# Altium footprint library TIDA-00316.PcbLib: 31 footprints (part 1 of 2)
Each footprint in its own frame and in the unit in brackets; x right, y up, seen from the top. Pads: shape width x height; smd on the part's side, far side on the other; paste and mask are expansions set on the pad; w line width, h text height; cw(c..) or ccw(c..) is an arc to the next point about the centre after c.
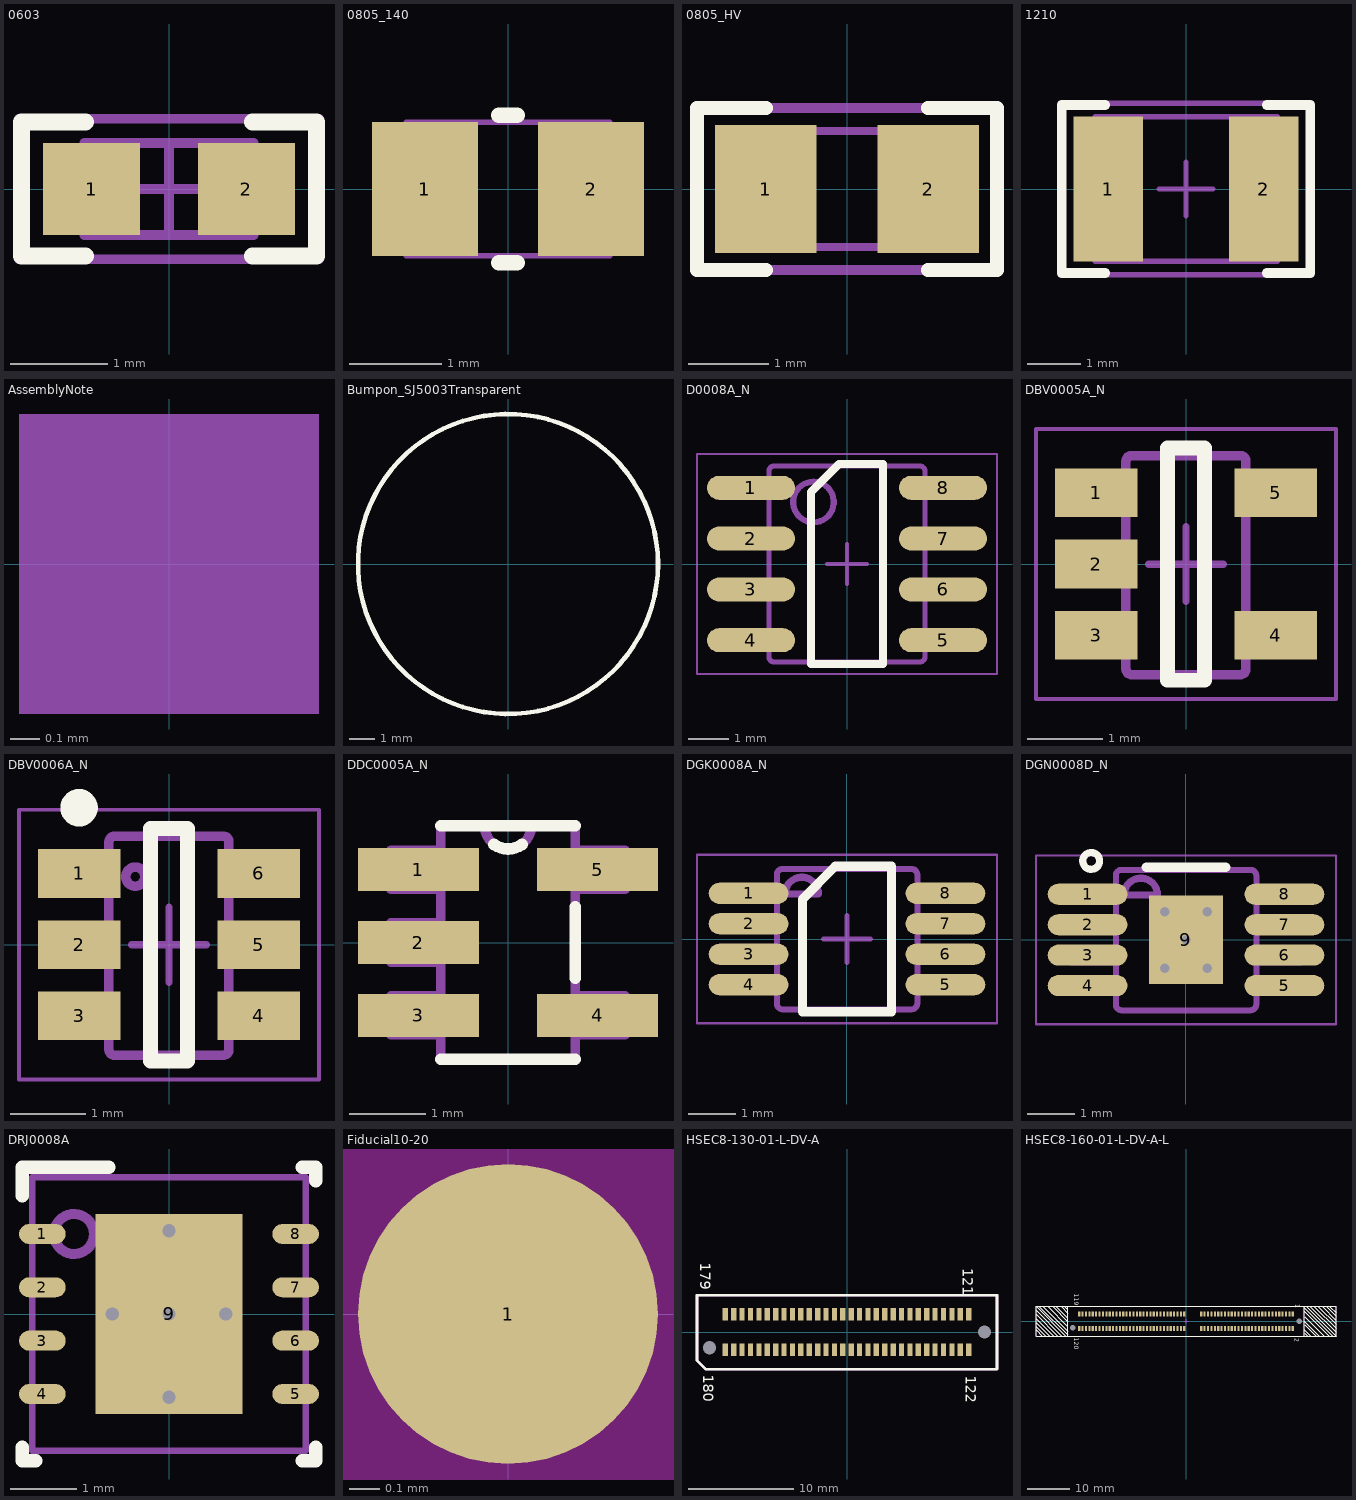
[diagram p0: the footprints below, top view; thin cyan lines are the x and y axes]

## 0603 [mm] "0603 from SM-752 data"
height 0.85
pads (2):
  rect 1x0.95 smd: 1(-0.8,0) 2(0.8,0)
Top Overlay:
  lines w0.178: -0.864,-0.691 -1.524,-0.691 -1.524,0.693 -0.864,0.693 ; 0.864,-0.691 1.524,-0.691 1.524,0.693 0.864,0.693
Mechanical 5:
  lines w0.1: -1.55,-0.725 1.55,-0.725 1.55,0.725 -1.55,0.725 -1.55,-0.725
  text ".Designator" at 0.863,0.462 h0.76
Mechanical 13:
  lines w0.1: -0.55,-0.475 -0.55,0.475 ; 0.55,-0.475 0.55,0.475 ; -0.875,-0.475 -0.875,0.475 0.875,0.475 0.875,-0.475 -0.875,-0.475
Mechanical 15:
  lines w0.1: -0.475,0 0.475,0 ; 0,-0.475 0,0.475 ; -1.55,-0.725 -1.55,0.725 1.55,0.725 1.55,-0.725 -1.55,-0.725
3D body: height 0.85, standoff 0, extent 0.551,-0.474 0.874,0.474
3D body: height 0.85, standoff 0, extent -0.549,-0.474 0.549,0.474
3D body: height 0.85, standoff 0, extent -0.874,-0.474 -0.551,0.474

## 0805_140 [mm] "0805 / 1.4mm height"
height 1.4
pads (2):
  rect 1.15x1.45 smd: 1(-0.9,0) 2(0.9,0)
Top Overlay:
  lines w0.17: -0.1,-0.8 0.1,-0.8 ; -0.1,0.8 0.1,0.8
Mechanical 5:
  lines w0.06: -1.1,-0.725 -1.1,0.725 1.1,0.725 1.1,-0.725 -1.1,-0.725
  text ".Designator" at -0.229,-0.305 h0.76
3D body: height 1.4, standoff 0, extent 0.501,-0.724 1.099,0.724
3D body: height 1.4, standoff 0, extent -0.499,-0.724 0.5,0.725
3D body: height 1.4, standoff 0, extent -1.099,-0.724 -0.501,0.724

## 0805_HV [mil] "0805 with 30mil clearance between pads"
height 43.31
pads (2):
  rect 50x63 smd: 1(-40,0) 2(40,0)
Top Overlay:
  lines w7: -40,-40 -74,-40 -74,0 -74,40 -40,40 ; 40,-40 74,-40 74,0 74,40 40,40
Mechanical 5:
  lines w5: -74,-40 -74,40 74,40 74,-40 -74,-40
  text ".Designator" at 24,11 h30
Mechanical 13:
  lines w3.94: -25.59,-28.54 -25.59,28.54 ; 25.59,-28.54 25.59,28.54 ; -43.31,-28.54 43.31,-28.54 43.31,28.54 -43.31,28.54 -43.31,-28.54
3D body: height 43.31, standoff 0, extent -43.29,-28.52 -25.61,28.52
3D body: height 43.31, standoff 0, extent -25.57,-28.52 25.57,28.52
3D body: height 43.31, standoff 0, extent 25.61,-28.52 43.29,28.52

## 1210 [mm] "1210 from SM-752 data"
height 1.35
pads (2):
  rect 1.3x2.7 smd: 1(-1.45,0) 2(1.45,0)
Top Overlay:
  lines w0.178: -1.511,-1.568 -2.316,-1.568 -2.316,1.568 -1.511,1.568 ; 1.511,-1.568 2.316,-1.568 2.316,1.568 1.511,1.568
Mechanical 5:
  lines w0.1: -1.7,-1.35 1.7,-1.35 1.7,1.35 -1.7,1.35 -1.7,-1.35
  text ".Designator" at 0.381,0.381 h0.76
Mechanical 13:
  lines w0.1: -1.2,-1.35 -1.2,1.35 ; 1.2,-1.35 1.2,1.35 ; -1.7,-1.35 -1.7,1.35 1.7,1.35 1.7,-1.35 -1.7,-1.35
Mechanical 15:
  lines w0.1: -0.5,0 0.5,0 ; 0,-0.5 0,0.5 ; -2.35,-1.6 -2.35,1.6 2.35,1.6 2.35,-1.6 -2.35,-1.6
3D body: height 1.35, standoff 0, extent -1.699,-1.349 -1.201,1.349
3D body: height 1.35, standoff 0, extent -1.199,-1.349 1.199,1.349
3D body: height 1.35, standoff 0, extent 1.201,-1.349 1.699,1.349

## AssemblyNote [mm] "Assembly Note"
Mechanical 5:
  rectangle: -0.508,-0.508 0.508,0.508
  text ".Comment" at 1.143,-0.508 h0.76
  text ".Designator" at -4.191,-0.508 h0.76

## Bumpon_SJ5003Transparent [mil] "3M Hemispherical Bumpon transparent"
height 200
pads (1):
  round 1 on Mech3: 0(0,0)
Top Overlay:
  circle w7: c0,0 r228.04
Mechanical 5:
  circle w5: c0,0 r228.04
  text ".Designator" at -60,-20 h30
3D body: height 196.82, standoff 0, extent -216.77,-218.07 218.51,218.08

## D0008A_N [mm] "SOIC, 8-Leads, Body 4.9x3.9mm, Pitch 1.27mm, IPC Medium Density"
height 1.75
pads (8):
  oval 2.2x0.6 smd: 1(-2.4,1.905) 2(-2.4,0.635) 3(-2.4,-0.635) 4(-2.4,-1.905) 5(2.4,-1.905) 6(2.4,-0.635) 7(2.4,0.635) 8(2.4,1.905)
Top Overlay:
  lines w0.2: -0.9,-2.5 -0.9,1.8 -0.2,2.5 0.9,2.5 0.9,-2.5 -0.9,-2.5
Mechanical 5:
  lines w0.127: -2.375,-2.095 -1.995,-2.095 -1.952,-2.095 -1.952,-1.715 -1.995,-1.715 -2.375,-1.715 ; -2.375,-2.095 -2.589,-2.095 -3.002,-2.095 -3.002,-1.715 -2.589,-1.715 -2.375,-1.715 ; -2.375,-2.095 -2.375,-1.715 ; -2.375,-0.825 -1.995,-0.825 -1.952,-0.825 -1.952,-0.445 -1.995,-0.445 -2.375,-0.445 ; -2.375,-0.825 -2.589,-0.825 -3.002,-0.825 -3.002,-0.445 -2.589,-0.445 -2.375,-0.445 ; -2.375,-0.825 -2.375,-0.445 ; -2.375,0.445 -1.995,0.445 -1.952,0.445 -1.952,0.825 -1.995,0.825 -2.375,0.825 ; -2.375,0.445 -2.589,0.445 -3.002,0.445 -3.002,0.825 -2.589,0.825 -2.375,0.825 ; -2.375,0.445 -2.375,0.825 ; -2.375,1.715 -1.995,1.715 -1.952,1.715 -1.952,2.095 -1.995,2.095 -2.375,2.095 ; -2.375,1.715 -2.589,1.715 -3.002,1.715 -3.002,2.095 -2.589,2.095 -2.375,2.095 ; -2.375,1.715 -2.375,2.095 ; -0.332,-2.45 -1.825,-2.45 -1.826,-2.45 cw(c-1.825,-2.323) -1.952,-2.324 -1.952,-2.323 -1.952,2.323 -1.952,2.324 cw(c-1.825,2.323) -1.826,2.45 -1.825,2.45 -0.332,2.45 ; -0.332,-2.45 -0.182,-2.45 ; -0.332,-2.45 -0.182,-2.45 ; -0.332,2.45 -0.182,2.45 ; -0.332,2.45 -0.182,2.45 ; -0.182,-2.45 0.178,-2.45 ; -0.182,2.45 0.178,2.45 ; 0.178,-2.45 0.328,-2.45 ; 0.178,-2.45 0.328,-2.45 ; 0.178,2.45 0.328,2.45 ; 0.178,2.45 0.328,2.45 ; 0.328,-2.45 1.821,-2.45 1.822,-2.45 ccw(c1.821,-2.323) 1.948,-2.324 1.948,-2.323 1.948,2.323 1.948,2.324 ccw(c1.821,2.323) 1.822,2.45 1.821,2.45 0.328,2.45 ; 2.371,-2.095 2.585,-2.095 2.998,-2.095 2.998,-1.715 2.585,-1.715 2.371,-1.715 ; 2.371,-2.095 1.991,-2.095 1.948,-2.095 1.948,-1.715 1.991,-1.715 2.371,-1.715 ; 2.371,-2.095 2.371,-1.715 ; 2.371,-0.825 2.585,-0.825 2.998,-0.825 2.998,-0.445 2.585,-0.445 2.371,-0.445 ; 2.371,-0.825 1.991,-0.825 1.948,-0.825 1.948,-0.445 1.991,-0.445 2.371,-0.445 ; 2.371,-0.825 2.371,-0.445 ; 2.371,0.445 2.585,0.445 2.998,0.445 2.998,0.825 2.585,0.825 2.371,0.825 ; 2.371,0.445 1.991,0.445 1.948,0.445 1.948,0.825 1.991,0.825 2.371,0.825 ; 2.371,0.445 2.371,0.825 ; 2.371,1.715 2.585,1.715 2.998,1.715 2.998,2.095 2.585,2.095 2.371,2.095 ; 2.371,1.715 1.991,1.715 1.948,1.715 1.948,2.095 1.991,2.095 2.371,2.095 ; 2.371,1.715 2.371,2.095
  lines w0.152: -0.838,1.041 cw(c-0.838,1.549) -0.838,2.057 cw(c-0.838,1.549) -0.838,1.041
  text ".Designator" at -0.889,-0.66 h0.76
Mechanical 15:
  lines w0.05: -3.75,-2.75 -3.75,2.75 3.75,2.75 3.75,-2.75 -3.75,-2.75
  lines w0.1: -0.5,0 0.5,0 ; 0,-0.5 0,0.5
3D body: height 1.63, standoff 0, extent -3,-2.45 3,2.45

## DBV0005A_N [mm] "SOT23, 5-Leads, Body 2.9x1.6mm, Pitch 0.95mm, Lead Span 2.8mm, IPC Medium Density"
height 1.45
pads (5):
  rect 1.1x0.65 smd: 1(-1.2,0.95) 2(-1.2,0) 3(-1.2,-0.95) 4(1.2,-0.95) 5(1.2,0.95)
Top Overlay:
  lines w0.2: -0.25,-1.55 0.25,-1.55 0.25,1.55 -0.25,1.55 -0.25,-1.55
Mechanical 5:
  lines w0.127: -0.801,1.371 cw(c-0.725,1.37) -0.725,1.446 ; -0.801,1.37 -0.801,-1.399 -0.801,-1.4 ccw(c-0.725,-1.399) -0.725,-1.475 ; -0.801,1.37 -0.801,1.371 ; -0.725,-1.475 -0.725,-1.475 ; -0.725,-1.475 0.723,-1.475 0.724,-1.475 ccw(c0.723,-1.399) 0.799,-1.4 0.799,-1.399 0.799,1.37 ; -0.725,1.446 0.723,1.446 0.724,1.446 cw(c0.723,1.37) 0.799,1.371 ; -0.725,1.446 -0.725,1.446 ; 0.799,1.37 0.799,1.371 ; -1.423,-1.167 -1.199,-1.167 -1.105,-1.167 -1.088,-1.167 -0.835,-1.167 -0.801,-1.167 -0.801,-0.767 -0.835,-0.767 -1.088,-0.767 -1.105,-0.767 -1.199,-0.767 -1.423,-0.767 -1.423,-1.167 ; -1.423,-0.215 -1.199,-0.215 -1.105,-0.215 -1.088,-0.215 -0.835,-0.215 -0.801,-0.215 -0.801,0.186 -0.835,0.186 -1.088,0.186 -1.105,0.186 -1.199,0.186 -1.423,0.186 -1.423,-0.215 ; -1.423,0.738 -1.199,0.738 -1.105,0.738 -1.088,0.738 -0.835,0.738 -0.801,0.738 -0.801,1.138 -0.835,1.138 -1.088,1.138 -1.105,1.138 -1.199,1.138 -1.423,1.138 -1.423,0.738 ; 0.799,-1.167 0.799,-0.767 0.834,-0.767 1.087,-0.767 1.103,-0.767 1.198,-0.767 1.422,-0.767 1.422,-1.167 1.198,-1.167 1.103,-1.167 1.087,-1.167 0.834,-1.167 0.799,-1.167 ; 0.799,0.738 0.799,1.138 0.834,1.138 1.087,1.138 1.103,1.138 1.198,1.138 1.422,1.138 1.422,0.738 1.198,0.738 1.103,0.738 1.087,0.738 0.834,0.738 0.799,0.738
  text ".Designator" at -0.356,0.889 h0.76
Mechanical 15:
  lines w0.05: -2,-1.8 -2,1.8 2,1.8 2,-1.8 -2,-1.8
  lines w0.1: -0.5,0 0.5,0 ; 0,-0.5 0,0.5
3D body: height 1.08, standoff -0.01, extent -1.422,-1.461 1.422,1.46

## DBV0006A_N [mm] "SOT23, 6-Leads, Body 2.9x1.6mm, Pitch 0.95mm, Lead Span 2.8mm, IPC Medium Density"
height 1.45
pads (6):
  rect 1.1x0.65 smd: 1(-1.2,0.95) 2(-1.2,0) 3(-1.2,-0.95) 4(1.2,-0.95) 5(1.2,0) 6(1.2,0.95)
Top Overlay:
  circle w0.25: c-1.2,1.825 r0.125
  lines w0.2: -0.25,-1.55 0.25,-1.55 0.25,1.55 -0.25,1.55 -0.25,-1.55
Mechanical 5:
  lines w0.127: 0.724,-1.475 ccw(c0.723,-1.399) 0.8,-1.399 0.8,1.37 ccw(c0.723,1.37) 0.724,1.446 ; 0.723,-1.475 0.724,-1.475 ; 0.723,-1.475 -0.724,-1.475 -0.725,-1.475 cw(c-0.724,-1.399) -0.801,-1.399 -0.801,1.37 cw(c-0.724,1.37) -0.725,1.446 -0.724,1.446 0.723,1.446 ; 0.723,1.446 0.724,1.446 ; -1.423,-1.154 -1.206,-1.154 -1.113,-1.154 -1.081,-1.154 -0.828,-1.154 -0.801,-1.154 -0.801,-0.78 -0.828,-0.78 -1.081,-0.78 -1.113,-0.78 -1.206,-0.78 -1.423,-0.78 -1.423,-1.154 ; -1.423,-0.202 -1.206,-0.202 -1.113,-0.202 -1.081,-0.202 -0.828,-0.202 -0.801,-0.202 -0.801,0.173 -0.828,0.173 -1.081,0.173 -1.113,0.173 -1.206,0.173 -1.423,0.173 -1.423,-0.202 ; -1.423,0.751 -1.206,0.751 -1.113,0.751 -1.081,0.751 -0.828,0.751 -0.801,0.751 -0.801,1.125 -0.828,1.125 -1.081,1.125 -1.113,1.125 -1.206,1.125 -1.423,1.125 -1.423,0.751 ; -0.577,0.906 cw(c-0.45,0.906) -0.323,0.906 cw(c-0.45,0.906) -0.577,0.906 ; 0.8,-1.154 0.827,-1.154 1.08,-1.154 1.112,-1.154 1.205,-1.154 1.422,-1.154 1.422,-0.78 1.205,-0.78 1.112,-0.78 1.08,-0.78 0.827,-0.78 0.8,-0.78 0.8,-1.154 ; 0.8,-0.202 0.827,-0.202 1.08,-0.202 1.112,-0.202 1.205,-0.202 1.422,-0.202 1.422,0.173 1.205,0.173 1.112,0.173 1.08,0.173 0.827,0.173 0.8,0.173 0.8,-0.202 ; 0.8,0.751 0.827,0.751 1.08,0.751 1.112,0.751 1.205,0.751 1.422,0.751 1.422,1.125 1.205,1.125 1.112,1.125 1.08,1.125 0.827,1.125 0.8,1.125 0.8,0.751
  text ".Designator" at 0.365,-1.295 h0.76
Mechanical 15:
  lines w0.05: -2,-1.8 -2,1.8 2,1.8 2,-1.8 -2,-1.8
  lines w0.1: -0.5,0 0.5,0 ; 0,-0.5 0,0.5
3D body: height 1.11, standoff -0.01, extent -1.422,-1.461 1.422,1.46

## DDC0005A_N [mil]
height 43.31
pads (5):
  rect 62x22 smd: 1(-46,37.4) 2(-46,0) 3(-46,-37.4) 4(46,-37.4) 5(46,37.4)
Top Overlay:
  lines w6: -34.5,-60 34.5,-60 ; -34.5,60 34.5,60 ; -7.14,50.35 ccw(c0,60) 7.14,50.35 ; 34.5,-18.3 34.5,18.3
Mechanical 5:
  lines w5: -12,60 ccw(c0,60) 12,60 ; -60,-47.4 -60,-27.4 -34.5,-27.4 -34.5,-47.4 -60,-47.4 ; -60,-10 -60,10 -34.5,10 -34.5,-10 -60,-10 ; -60,27.4 -60,47.4 -34.5,47.4 -34.5,27.4 -60,27.4 ; -34.5,-60 34.5,-60 34.5,60 -34.5,60 -34.5,-60 ; 34.5,-47.4 34.5,-27.4 60,-27.4 60,-47.4 34.5,-47.4 ; 34.5,27.4 34.5,47.4 60,47.4 60,27.4 34.5,27.4
  text ".Designator" at -16,23 h30
3D body: height 23.62, standoff 0, extent -59.98,-47.38 -34.52,-27.42
3D body: height 23.62, standoff 0, extent -59.98,27.42 -34.52,47.38
3D body: height 23.62, standoff 0, extent 34.52,-47.38 59.98,-27.42
3D body: height 23.62, standoff 0, extent 34.52,27.42 59.98,47.38
3D body: height 23.62, standoff 0, extent -59.98,-9.98 -34.52,9.98
3D body: height 43.31, standoff 0, extent -34.48,-59.98 34.48,59.98
3D body: height 43.31, standoff 0, extent -34.5,47.74 34.52,60.02

## DGK0008A_N [mm] "TSOP, 8-Leads, Body 3x3mm, Pitch 0.65mm, IPC Medium Density"
height 1.1
pads (8):
  oval 1.7x0.45 smd mask+0.05: 1(-2.1,0.975) 2(-2.1,0.325) 3(-2.1,-0.325) 4(-2.1,-0.975) 5(2.1,-0.975) 6(2.1,-0.325) 7(2.1,0.325) 8(2.1,0.975)
Top Overlay:
  lines w0.2: -0.95,-1.55 0.95,-1.55 0.95,1.55 -0.25,1.55 -0.95,0.85 -0.95,-1.55
Mechanical 5:
  lines w0.127: -2.45,-1.131 -2.21,-1.131 -2.091,-1.131 -2.087,-1.131 -1.784,-1.131 -1.498,-1.131 -1.498,-0.826 -1.784,-0.826 -2.087,-0.826 -2.091,-0.826 -2.21,-0.826 -2.45,-0.826 -2.45,-1.131 ; -2.45,-0.48 -2.21,-0.48 -2.091,-0.48 -2.087,-0.48 -1.784,-0.48 -1.498,-0.48 -1.498,-0.175 -1.784,-0.175 -2.087,-0.175 -2.091,-0.175 -2.21,-0.175 -2.45,-0.175 -2.45,-0.48 ; -2.45,0.17 -2.21,0.17 -2.091,0.17 -2.087,0.17 -1.784,0.17 -1.498,0.17 -1.498,0.475 -1.784,0.475 -2.087,0.475 -2.091,0.475 -2.21,0.475 -2.45,0.475 -2.45,0.17 ; -2.45,0.82 -2.21,0.82 -2.091,0.82 -2.087,0.82 -1.784,0.82 -1.498,0.82 -1.498,1.125 -1.784,1.125 -2.087,1.125 -2.091,1.125 -2.21,1.125 -2.45,1.125 -2.45,0.82 ; -1.497,-1.377 ccw(c-1.37,-1.374) -1.373,-1.501 -1.371,-1.501 1.373,-1.501 1.375,-1.501 ccw(c1.373,-1.374) 1.5,-1.377 1.5,-1.374 1.5,1.369 1.5,1.372 ccw(c1.373,1.369) 1.375,1.496 1.373,1.496 -1.371,1.496 -1.373,1.496 ccw(c-1.37,1.369) -1.497,1.372 -1.498,1.369 -1.498,-1.374 -1.497,-1.377 ; 1.5,-1.131 1.5,-0.826 1.786,-0.826 2.089,-0.826 2.093,-0.826 2.213,-0.826 2.452,-0.826 2.452,-1.131 2.213,-1.131 2.093,-1.131 2.089,-1.131 1.786,-1.131 1.5,-1.131 ; 1.5,-0.48 1.5,-0.175 1.786,-0.175 2.089,-0.175 2.093,-0.175 2.213,-0.175 2.452,-0.175 2.452,-0.48 2.213,-0.48 2.093,-0.48 2.089,-0.48 1.786,-0.48 1.5,-0.48 ; 1.5,0.17 1.5,0.475 1.786,0.475 2.089,0.475 2.093,0.475 2.213,0.475 2.452,0.475 2.452,0.17 2.213,0.17 2.093,0.17 2.089,0.17 1.786,0.17 1.5,0.17 ; 1.5,0.82 1.5,1.125 1.786,1.125 2.089,1.125 2.093,1.125 2.213,1.125 2.452,1.125 2.452,0.82 2.213,0.82 2.093,0.82 2.089,0.82 1.786,0.82 1.5,0.82
  lines w0.152: -1.32,0.962 cw(c-0.964,0.962) -0.609,0.962 -1.32,0.962
  text ".Designator" at -0.869,-0.508 h0.76
Mechanical 15:
  lines w0.05: -3.2,-1.8 -3.2,1.8 3.2,1.8 3.2,-1.8 -3.2,-1.8
  lines w0.1: -0.5,0 0.5,0 ; 0,-0.5 0,0.5
3D body: height 0.94, standoff -0.02, extent -2.451,-1.499 2.451,1.498

## DGN0008D_N [mm] "TSOP, 8-Leads, Body 3x3mm, Pitch 0.65mm, Thermal Pad 1.89x1.57mm, IPC Medium Density"
height 1.1
pads (9):
  oval 1.7x0.45 smd mask+0.064: 1(-2.1,0.975) 2(-2.1,0.325) 3(-2.1,-0.325) 4(-2.1,-0.975) 5(2.1,-0.975) 6(2.1,-0.325) 7(2.1,0.325) 8(2.1,0.975)
  rect 1.57x1.89 smd: 9(0,0)
via 0.45,-0.6 diameter 0.5 hole 0.2
via 0.45,0.6 diameter 0.5 hole 0.2
via -0.45,-0.6 diameter 0.5 hole 0.2
via 0,0 diameter 0.5 hole 0.2
via -0.45,0.6 diameter 0.5 hole 0.2
Top Overlay:
  circle w0.152: c-2.023,1.686 r0.18
  lines w0.2: -0.85,1.55 0.85,1.55
Mechanical 5:
  lines w0.127: -2.45,-1.131 -2.21,-1.131 -2.09,-1.131 -2.087,-1.131 -1.784,-1.131 -1.498,-1.131 -1.498,-0.826 -1.784,-0.826 -2.087,-0.826 -2.09,-0.826 -2.21,-0.826 -2.45,-0.826 -2.45,-1.131 ; -2.45,-0.48 -2.21,-0.48 -2.09,-0.48 -2.087,-0.48 -1.784,-0.48 -1.498,-0.48 -1.498,-0.175 -1.784,-0.175 -2.087,-0.175 -2.09,-0.175 -2.21,-0.175 -2.45,-0.175 -2.45,-0.48 ; -2.45,0.17 -2.21,0.17 -2.09,0.17 -2.087,0.17 -1.784,0.17 -1.498,0.17 -1.498,0.475 -1.784,0.475 -2.087,0.475 -2.09,0.475 -2.21,0.475 -2.45,0.475 -2.45,0.17 ; -2.45,0.82 -2.21,0.82 -2.09,0.82 -2.087,0.82 -1.784,0.82 -1.498,0.82 -1.498,1.125 -1.784,1.125 -2.087,1.125 -2.09,1.125 -2.21,1.125 -2.45,1.125 -2.45,0.82 ; -1.497,-1.377 ccw(c-1.37,-1.374) -1.373,-1.501 -1.371,-1.501 1.373,-1.501 1.375,-1.501 ccw(c1.373,-1.374) 1.5,-1.377 1.5,-1.374 1.5,1.369 1.5,1.372 ccw(c1.373,1.369) 1.375,1.496 1.373,1.496 -1.371,1.496 -1.373,1.496 ccw(c-1.37,1.369) -1.497,1.372 -1.498,1.369 -1.498,-1.374 -1.497,-1.377 ; 1.5,-1.131 1.5,-0.826 1.786,-0.826 2.089,-0.826 2.093,-0.826 2.213,-0.826 2.452,-0.826 2.452,-1.131 2.213,-1.131 2.093,-1.131 2.089,-1.131 1.786,-1.131 1.5,-1.131 ; 1.5,-0.48 1.5,-0.175 1.786,-0.175 2.089,-0.175 2.093,-0.175 2.213,-0.175 2.452,-0.175 2.452,-0.48 2.213,-0.48 2.093,-0.48 2.089,-0.48 1.786,-0.48 1.5,-0.48 ; 1.5,0.17 1.5,0.475 1.786,0.475 2.089,0.475 2.093,0.475 2.213,0.475 2.452,0.475 2.452,0.17 2.213,0.17 2.093,0.17 2.089,0.17 1.786,0.17 1.5,0.17 ; 1.5,0.82 1.5,1.125 1.786,1.125 2.089,1.125 2.093,1.125 2.213,1.125 2.452,1.125 2.452,0.82 2.213,0.82 2.093,0.82 2.089,0.82 1.786,0.82 1.5,0.82
  lines w0.152: -1.32,0.962 cw(c-0.964,0.962) -0.609,0.962 -1.32,0.962
  text ".Designator" at 0.744,-1.768 h0.76
Mechanical 15:
  lines w0.05: -3.2,-1.8 -3.2,1.8 3.2,1.8 3.2,-1.8 -3.2,-1.8
  lines w0.1: -0.5,0 0.5,0 ; 0,-0.5 0,0.5
3D body: height 0.94, standoff -0.02, extent -2.451,-1.499 2.451,1.498

## DRJ0008A [mm] "SON, 8-Leads, Body 4x4mm, Pitch 0.8mm, Thermal Pad 3x2.2mm, TI Recommended"
height 0.8
pads (9):
  oval 0.7x0.3 smd: 1(-1.9,1.2) 2(-1.9,0.4) 3(-1.9,-0.4) 4(-1.9,-1.2) 5(1.9,-1.2) 6(1.9,-0.4) 7(1.9,0.4) 8(1.9,1.2)
  rect 2.2x3 smd paste-1.1: 9(0,0)
via 0.85,0 diameter 0.5 hole 0.2
via 0,0 diameter 0.5 hole 0.2
via 0,1.25 diameter 0.5 hole 0.2
via 0,-1.25 diameter 0.5 hole 0.2
via -0.85,0 diameter 0.5 hole 0.2
Top Overlay:
  lines w0.2: -2.2,-2 -2.2,-2.2 -2,-2.2 ; -2.2,1.775 -2.2,2.2 -0.9,2.2 ; 2,-2.2 2.2,-2.2 2.2,-2 ; 2,2.2 2.2,2.2 2.2,2
Top Paste:
  rectangle: 0.1,0.1 1.081,1.41
  region: -0.1,1.41 -1.081,1.41 -1.081,0.1 -0.1,0.1
  region: -0.1,-0.1 -1.081,-0.1 -1.081,-1.41 -0.1,-1.41
  rectangle: 0.1,-1.41 1.081,-0.1
Mechanical 5:
  circle w0.152: c-1.425,1.2 r0.3
  lines w0.1: -2.05,-2.05 2.05,-2.05 2.05,2.05 -2.05,2.05 -2.05,-2.05
  text ".Designator" at -0.635,2.362 h1.02
3D body: height 0.8, standoff 0, extent -2.05,-2.05 2.05,2.05
3D body: height 0.81, standoff 0.5, extent -1.73,0.895 -1.12,1.505

## Fiducial10-20 [mm]
pads (1):
  round 1 smd mask+0.5: 1(0,0)
Top Layer keep-out:
  circle w1.178: c0,0 r0.5

## HSEC8-130-01-L-DV-A [mm]
pads (62):
  rect 0.5x1.2 smd: 121(11.6,1.7) 122(11.6,-1.7) 123(10.8,1.7) 124(10.8,-1.7) 125(10,1.7) 126(10,-1.7) 127(9.2,1.7) 128(9.2,-1.7) 129(8.4,1.7) 130(8.4,-1.7) 131(7.6,1.7) 132(7.6,-1.7) 133(6.8,1.7) 134(6.8,-1.7) 135(6,1.7) 136(6,-1.7) 137(5.2,1.7) 138(5.2,-1.7) 139(4.4,1.7) 140(4.4,-1.7) 141(3.6,1.7) 142(3.6,-1.7) 143(2.8,1.7) 144(2.8,-1.7) 145(2,1.7) 146(2,-1.7) 147(1.2,1.7) 148(1.2,-1.7) 149(0.4,1.7) 150(0.4,-1.7) 151(-0.4,1.7) 152(-0.4,-1.7) 153(-1.2,1.7) 154(-1.2,-1.7) 155(-2,1.7) 156(-2,-1.7) 157(-2.8,1.7) 158(-2.8,-1.7) 159(-3.6,1.7) 160(-3.6,-1.7) 161(-4.4,1.7) 162(-4.4,-1.7) 163(-5.2,1.7) 164(-5.2,-1.7) 165(-6,1.7) 166(-6,-1.7) 167(-6.8,1.7) 168(-6.8,-1.7) 169(-7.6,1.7) 170(-7.6,-1.7) 171(-8.4,1.7) 172(-8.4,-1.7) 173(-9.2,1.7) 174(-9.2,-1.7) 175(-10,1.7) 176(-10,-1.7) 177(-10.8,1.7) 178(-10.8,-1.7) 179(-11.6,1.7) 180(-11.6,-1.7)
  round 0 hole 1.27 unplated mask+0.889: 181(13.1,0) 182(-13.1,-1.5)
Top Overlay:
  lines w0.254: 14.246,-3.554 -13.464,-3.554 -14.3,-2.718 -14.3,1.75 -14.3,3.5 ; 14.3,-3.5 14.3,3.5 ; -14.3,3.5 14.3,3.5 ; -14.3,3.5 14.3,3.5
  text "122" at 11.303,-4.191 h1.02
  text "121" at 11.049,6.096 h1.02
  text "179" at -14.007,6.608 h1.02
  text "180" at -13.716,-4.064 h1.02
Mechanical 5:
  lines w0.254: 14.246,-3.554 -13.464,-3.554 -14.3,-2.718 -14.3,1.75 -14.3,3.5 14.3,3.5 14.3,-3.5
Mechanical 13:
  lines w0.1: -14.3,-2.7 -14.3,3.5 14.3,3.5 14.3,-3.5 -13.5,-3.5 -14.3,-2.7

## HSEC8-160-01-L-DV-A-L [mm] "CONN HIGH SPD CARD EDGE 120 POS"
height 12.4
pads (122):
  rect 0.5x1.2 smd: 1(25.2,1.7) 2(25.2,-1.7) 3(24.4,1.7) 4(24.4,-1.7) 5(23.6,1.7) 6(23.6,-1.7) 7(22.8,1.7) 8(22.8,-1.7) 9(22,1.7) 10(22,-1.7) 11(21.2,1.7) 12(21.2,-1.7) 13(20.4,1.7) 14(20.4,-1.7) 15(19.6,1.7) 16(19.6,-1.7) 17(18.8,1.7) 18(18.8,-1.7) 19(18,1.7) 20(18,-1.7) 21(17.2,1.7) 22(17.2,-1.7) 23(16.4,1.7) 24(16.4,-1.7) 25(15.6,1.7) 26(15.6,-1.7) 27(14.8,1.7) 28(14.8,-1.7) 29(14,1.7) 30(14,-1.7) 31(13.2,1.7) 32(13.2,-1.7) 33(12.4,1.7) 34(12.4,-1.7) 35(11.6,1.7) 36(11.6,-1.7) 37(10.8,1.7) 38(10.8,-1.7) 39(10,1.7) 40(10,-1.7) 41(9.2,1.7) 42(9.2,-1.7) 43(8.4,1.7) 44(8.4,-1.7) 45(7.6,1.7) 46(7.6,-1.7) 47(6.8,1.7) 48(6.8,-1.7) 49(6,1.7) 50(6,-1.7) 51(5.2,1.7) 52(5.2,-1.7) 53(4.4,1.7) 54(4.4,-1.7) 55(3.6,1.7) 56(3.6,-1.7) 57(-0.4,1.7) 58(-0.4,-1.7) 59(-1.2,1.7) 60(-1.2,-1.7) 61(-2,1.7) 62(-2,-1.7) 63(-2.8,1.7) 64(-2.8,-1.7) 65(-3.6,1.7) 66(-3.6,-1.7) 67(-4.4,1.7) 68(-4.4,-1.7) 69(-5.2,1.7) 70(-5.2,-1.7) 71(-6,1.7) 72(-6,-1.7) 73(-6.8,1.7) 74(-6.8,-1.7) 75(-7.6,1.7) 76(-7.6,-1.7) 77(-8.4,1.7) 78(-8.4,-1.7) 79(-9.2,1.7) 80(-9.2,-1.7) 81(-10,1.7) 82(-10,-1.7) 83(-10.8,1.7) 84(-10.8,-1.7) 85(-11.6,1.7) 86(-11.6,-1.7) 87(-12.4,1.7) 88(-12.4,-1.7) 89(-13.2,1.7) 90(-13.2,-1.7) 91(-14,1.7) 92(-14,-1.7) 93(-14.8,1.7) 94(-14.8,-1.7) 95(-15.6,1.7) 96(-15.6,-1.7) 97(-16.4,1.7) 98(-16.4,-1.7) 99(-17.2,1.7) 100(-17.2,-1.7) 101(-18,1.7) 102(-18,-1.7) 103(-18.8,1.7) 104(-18.8,-1.7) 105(-19.6,1.7) 106(-19.6,-1.7) 107(-20.4,1.7) 108(-20.4,-1.7) 109(-21.2,1.7) 110(-21.2,-1.7) 111(-22,1.7) 112(-22,-1.7) 113(-22.8,1.7) 114(-22.8,-1.7) 115(-23.6,1.7) 116(-23.6,-1.7) 117(-24.4,1.7) 118(-24.4,-1.7) 119(-25.2,1.7) 120(-25.2,-1.7)
  round 0 hole 1.27 unplated mask+0.889: 121(-26.7,-1.5) 122(26.7,0)
Top Overlay:
  lines w0.2: -35.4,-2.032 -33.909,-3.523 ; -35.4,-1.27 -33.114,-3.556 ; -35.4,0.635 -31.242,-3.523 ; -35.4,1.651 -30.226,-3.523 ; -35.4,2.54 -29.337,-3.523 ; -35.353,-0.334 -32.131,-3.556 ; -34.58,3.465 -27.94,-3.175 ; -33.782,3.5 -27.9,-2.382 ; -32.639,3.5 -27.996,-1.143 ; -31.496,3.5 -27.9,-0.096 ; -30.734,3.5 -27.996,0.762 ; -29.464,3.5 -27.9,1.936 ; -28.702,3.5 -27.996,2.794 ; -28.344,-3.556 -35.4,3.5 ; -27.773,3.5 28.027,3.5 ; 27.773,3.5 35.273,3.5 ; 27.9,-1.992 29.464,-3.556 ; 27.9,0.04 31.496,-3.556 ; 27.9,2.326 33.782,-3.556 ; 27.94,3.119 34.58,-3.52 ; 27.996,-2.85 28.702,-3.556 ; 27.996,-0.818 30.734,-3.556 ; 27.996,1.087 32.639,-3.556 ; 28.344,3.5 35.4,-3.556 ; 29.337,3.467 35.4,-2.596 ; 30.226,3.467 35.4,-1.707 ; 31.242,3.467 35.4,-0.691 ; 32.131,3.5 35.353,0.278 ; 33.114,3.5 35.4,1.214 ; 33.909,3.467 35.4,1.976 ; 35.4,3.5 35.4,-3.556 ; -35.4,3.5 -27.9,3.5 -27.9,-3.556 ; -35.4,3.5 -35.4,-3.556 -27.9,-3.556 ; -27.9,-3.556 27.9,-3.556 ; 27.9,-3.556 27.9,3.5 27.9,-3.556 ; 27.9,-3.556 35.4,-3.556
  text "2" at 25.698,-4.039 h1.02
  text "1" at 25.825,4.039 h1.02
  text "119" at -26.372,6.426 h1.02
  text "120" at -26.372,-3.856 h1.02
Mechanical 5:
  lines w0.2: -27.9,-3.556 27.9,-3.556 ; -27.9,-3.556 -27.9,3.5 ; -27.9,-3.556 -35.4,-3.556 -35.4,3.5 -27.9,3.5 ; -27.9,3.5 27.9,3.5 ; 27.9,-3.556 35.4,-3.556 35.4,3.5 27.9,3.5 ; 27.9,-3.556 27.9,3.5
Mechanical 13:
  lines w0.1: 27.9,-3.556 27.9,3.444 ; -27.9,-3.5 -27.9,3.5 27.9,3.5 27.9,-3.5 -27.9,-3.5
Mechanical 15:
  lines w0.1: -0.5,0 0.5,0 ; 0,-0.5 0,0.5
